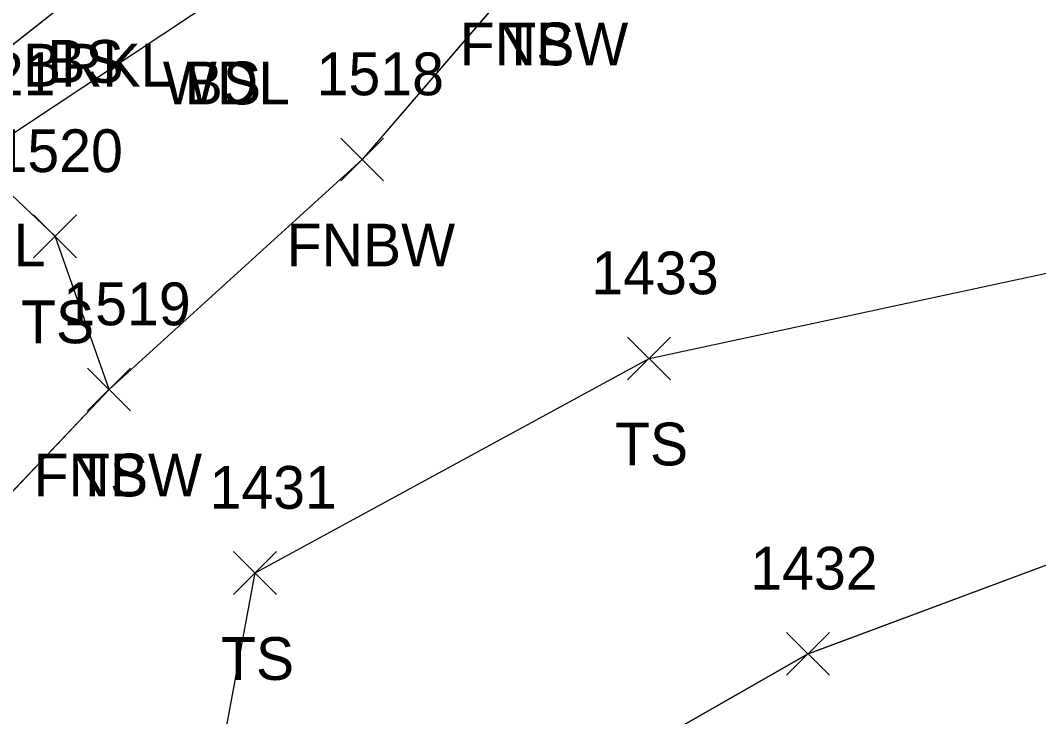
# Model space of a CAD drawing. Extents: x 1415642 to 1422021, y 544543 to 547232.
# Drawn here: x 1416089.95 to 1416137.53, y 546718.3 to 546750.85 of the extents above; entities that cross this region are included whole.
import ezdxf

# ---------------------------------------------------------------- set-up
doc = ezdxf.new("R2010")
doc.units = 0
for name, color, linetype in [('L_A', 7, 'Continuous'), ('L_I', 7, 'Continuous'), ('L_TIC', 7, 'Continuous'), ('LAWA', 7, 'Continuous'), ('LAWE', 7, 'Continuous'), ('LELB', 7, 'Continuous'), ('LFNC', 7, 'Continuous')]:
    doc.layers.add(name, color=color, linetype=linetype)

msp = doc.modelspace()

# ---------------------------------------------------------------- linework, layer by layer
at = {"layer": 'L_TIC'}
for points in [[(1416104.919, 546743.351), (1416106.919, 546745.351)], [(1416106.919, 546743.351), (1416104.919, 546745.351)], [(1416090.572, 546739.759), (1416092.572, 546741.759)], [(1416092.572, 546739.759), (1416090.572, 546741.759)], [(1416118.322, 546734.048), (1416120.322, 546736.048)], [(1416120.322, 546734.048), (1416118.322, 546736.048)], [(1416093.093, 546732.599), (1416095.093, 546734.599)], [(1416095.093, 546732.599), (1416093.093, 546734.599)], [(1416093.093, 546732.599), (1416095.093, 546734.599)], [(1416095.093, 546732.599), (1416093.093, 546734.599)], [(1416099.915, 546724.021), (1416101.915, 546726.021)], [(1416101.915, 546724.021), (1416099.915, 546726.021)], [(1416125.749, 546720.244), (1416127.749, 546722.244)], [(1416127.749, 546720.244), (1416125.749, 546722.244)]]:
    msp.add_lwpolyline(points, dxfattribs=at)
at = {"layer": 'LAWA'}
for points in [[(1416189.468, 546748.093), (1416170.483, 546756.813), (1416159.398, 546761.07), (1416158.818, 546764.495), (1416158.5, 546767.312), (1416157.339, 546771.4), (1416149.111, 546783.522), (1416143.568, 546776.625), (1416135.571, 546781.553), (1416136.009, 546776.955), (1416135.395, 546775.051), (1416133.212, 546773.698), (1416124.824, 546771.254), (1416110.474, 546763.899), (1416099.189, 546751.925), (1416087.771, 546744.353), (1416077.131, 546736.348), (1416057.108, 546720.869), (1416047.173, 546704.924)], [(1416189.464, 546748.092), (1416170.487, 546756.813), (1416159.394, 546761.071), (1416158.815, 546764.495), (1416158.505, 546767.312), (1416157.342, 546771.4), (1416149.113, 546783.521), (1416143.565, 546776.626), (1416135.574, 546781.553), (1416136.011, 546776.955), (1416135.402, 546775.05), (1416133.216, 546773.698), (1416124.826, 546771.255), (1416110.476, 546763.9), (1416099.195, 546751.924), (1416087.779, 546744.35), (1416077.137, 546736.347), (1416057.114, 546720.867), (1416047.178, 546704.926)]]:
    msp.add_lwpolyline(points, dxfattribs=at)
at = {"layer": 'LAWE'}
for points in [[(1416039.047, 546718.337), (1416052.784, 546723.735), (1416060.875, 546726.975), (1416074.377, 546737.683), (1416086.319, 546747.157), (1416093.425, 546752.758), (1416101.98, 546759.616), (1416111.397, 546767.511), (1416119.583, 546772.235), (1416127.403, 546776.082), (1416128.271, 546778.626), (1416129.002, 546780.644), (1416128.144, 546784.491), (1416130.448, 546789.914), (1416132.468, 546795.001), (1416130.863, 546797.224), (1416127.694, 546798.829)], [(1416039.053, 546718.334), (1416052.787, 546723.738), (1416060.879, 546726.977), (1416074.38, 546737.685), (1416086.328, 546747.153), (1416093.43, 546752.758), (1416101.985, 546759.615), (1416111.399, 546767.512), (1416119.591, 546772.233), (1416127.408, 546776.081), (1416128.28, 546778.625), (1416129.011, 546780.643), (1416128.148, 546784.491), (1416130.455, 546789.913), (1416132.475, 546795.001), (1416130.871, 546797.224), (1416127.702, 546798.828)]]:
    msp.add_lwpolyline(points, dxfattribs=at)
at = {"layer": 'LELB'}
for points in [[(1416094.974, 546692.98), (1416100.915, 546725.021), (1416119.322, 546735.048), (1416143.84, 546740.317), (1416158.08, 546750.444), (1416159.398, 546761.07), (1416139.079, 546763.942), (1416114.009, 546753.752)], [(1416094.979, 546692.982), (1416100.917, 546725.022), (1416119.325, 546735.049), (1416143.845, 546740.318), (1416158.084, 546750.445), (1416159.394, 546761.071), (1416139.085, 546763.941), (1416114.011, 546753.753)], [(1416175.936, 546741.204), (1416165.363, 546727), (1416147.251, 546707.905), (1416122.505, 546691.802), (1416094.974, 546692.98), (1416111.597, 546712.582), (1416126.749, 546721.244), (1416149.596, 546729.765), (1416158.08, 546750.444)], [(1416175.932, 546741.204), (1416165.361, 546727), (1416147.255, 546707.906), (1416122.504, 546691.802), (1416094.979, 546692.982), (1416111.6, 546712.583), (1416126.753, 546721.246), (1416149.597, 546729.766), (1416158.084, 546750.445)], [(1416094.093, 546733.599), (1416091.572, 546740.759), (1416087.771, 546744.353)], [(1416094.099, 546733.598), (1416091.578, 546740.758), (1416087.779, 546744.35)]]:
    msp.add_lwpolyline(points, dxfattribs=at)
at = {"layer": 'LFNC'}
for points in [[(1416124.612, 546767.204), (1416114.009, 546753.752), (1416105.919, 546744.351), (1416094.093, 546733.599), (1416082.302, 546721.158), (1416072.387, 546709.508)], [(1416124.618, 546767.203), (1416114.011, 546753.753), (1416105.922, 546744.352), (1416094.099, 546733.598), (1416082.31, 546721.154), (1416072.394, 546709.506)]]:
    msp.add_lwpolyline(points, dxfattribs=at)

# ---------------------------------------------------------------- texts
at = {"layer": 'L_A'}
for s, p in [('FNBW', (1416110.482, 546748.752)), ('TS', (1416112.419, 546748.752)), ('BS', (1416091.207, 546747.935)), ('BRKL', (1416090.071, 546747.758)), ('WDL', (1416096.606, 546746.925)), ('BS', (1416097.63, 546746.925)), ('WDL', (1416085.188, 546739.353)), ('FNBW', (1416102.391, 546739.351)), ('TS', (1416089.981, 546735.759)), ('TS', (1416117.732, 546730.048)), ('FNBW', (1416090.566, 546728.599)), ('TS', (1416092.503, 546728.599)), ('TS', (1416099.324, 546720.021))]:
    msp.add_text(s, height=2, dxfattribs=at).set_placement(p)
at = {"layer": 'L_I'}
for s, p in [('1521', (1416085.645, 546747.353)), ('1521', (1416085.645, 546747.353)), ('1521', (1416085.645, 546747.353)), ('1518', (1416103.793, 546747.351)), ('1520', (1416088.792, 546743.759)), ('1433', (1416116.629, 546738.048)), ('1519', (1416091.959, 546736.599)), ('1519', (1416091.959, 546736.599)), ('1431', (1416098.789, 546728.021)), ('1432', (1416124.056, 546724.244))]:
    msp.add_text(s, height=2, dxfattribs=at).set_placement(p)

doc.saveas('drawing.dxf')
